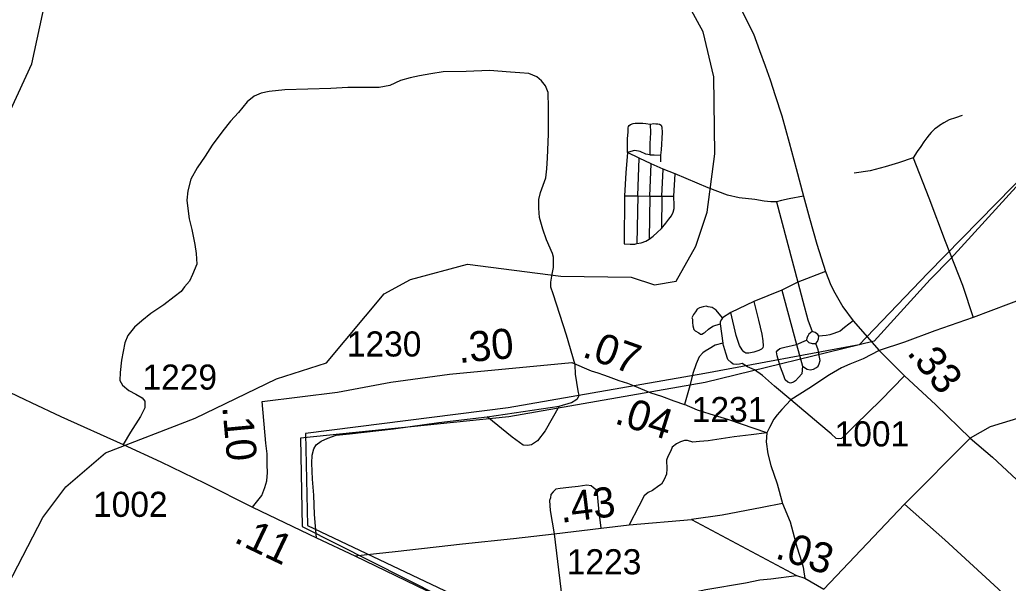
# Model space of a CAD drawing. Extents: x 2290615 to 2522933, y 819489 to 1012715.
# Drawn here: x 2388155 to 2393085, y 888136 to 890944 of the extents above; entities that cross this region are included whole.
import ezdxf

# ---------------------------------------------------------------- set-up
doc = ezdxf.new("R2010")
doc.units = 0
for name, color, linetype in [('Exist Boundary Political City Limit New', 7, 'Continuous'), ('Exist Boundary Political City Limit Old', 7, 'Continuous'), ('Exist Hydrographic Misc Water Feature', 7, 'Continuous'), ('Exist Road Non-System Type 51', 7, 'Continuous'), ('Exist Road Primary NC Attributed', 7, 'Continuous'), ('Exist Road Primary NC Service Mileage Hundredths English Label', 7, 'Continuous'), ('Exist Road Secondary Mileage Hundredths English Label', 7, 'Continuous'), ('Exist Road Secondary Type 51 Attributed', 7, 'Continuous'), ('Exist Road Secondary Type 51 Number Label', 7, 'Continuous'), ('Map Preparation Boundary City Limit Buffer Line', 7, 'Continuous')]:
    doc.layers.add(name, color=color, linetype=linetype)

msp = doc.modelspace()

# ---------------------------------------------------------------- linework, layer by layer
at = {"layer": 'Exist Boundary Political City Limit New'}
msp.add_lwpolyline([(2393362.8, 890373.7), (2392798.4, 889753.9), (2392694.9, 889650.5), (2392416.3, 889342.7), (2391572.9, 889137), (2390593.4, 888966), (2389555.6, 888859.2), (2389564.2, 888418.8), (2390596.7, 887898.2), (2389956.2, 887761.5), (2390068.6, 886905.3)], dxfattribs=at)
at = {"layer": 'Exist Boundary Political City Limit Old'}
msp.add_lwpolyline([(2393362.8, 890373.7), (2392684.2, 889680.7), (2392341, 889324.3), (2391571, 889182.1), (2390591.5, 889011.1), (2389579.5, 888881.7), (2389589.6, 888423.9), (2390631.3, 887930.1), (2390631.8, 887929.9)], dxfattribs=at)
at = {"layer": 'Exist Hydrographic Misc Water Feature'}
for points in [[(2383748.3, 888971.7), (2384365.3, 888954.3), (2385105.3, 889047.1), (2385735.3, 889315.7), (2386132.2, 889529), (2386581.2, 889704), (2386835.3, 889849), (2387338.5, 890082.2), (2387673.2, 890156.7), (2387970.3, 890352.8), (2388110.4, 890496.3), (2388215.4, 890723.8), (2388349.3, 891339.9), (2388438.3, 891550.4), (2388619.3, 891728.4), (2388801.2, 891837.6)], [(2387945.3, 887837.2), (2388270.3, 888464.4), (2388385.4, 888616.8), (2388583.2, 888785.7), (2389030.2, 888958.4), (2389436.2, 889155.5), (2389685.4, 889234.6), (2389972.3, 889578), (2390104.3, 889649), (2390387.3, 889726.3), (2390854.2, 889666.5), (2391204.2, 889661.2), (2391321.3, 889623.4), (2391429.4, 889640.9), (2391527.2, 889815.6), (2391583.3, 889985.4), (2391621.3, 890275.8), (2391616.4, 890659.6), (2391563.3, 890883.9), (2391306.3, 891356), (2391143.3, 891736.7), (2391133.3, 891861)]]:
    msp.add_lwpolyline(points, dxfattribs=at)
at = {"layer": 'Exist Road Non-System Type 51'}
for p, q in [((2391244.7, 890254.1), (2391185.8, 890282.7)), ((2391350.4, 890268.6), (2391351.2, 890235.5)), ((2391237.6, 890067.1), (2391244.7, 890254.1)), ((2391303.7, 890225.4), (2391244.7, 890254.1)), ((2391296.5, 890065.6), (2391303.7, 890225.4)), ((2391364, 890200.1), (2391303.7, 890225.4)), ((2391356.8, 890065.6), (2391364, 890200.1)), ((2391423, 890175.7), (2391364, 890200.1)), ((2391417.2, 890064.2), (2391423, 890175.7)), ((2391171.5, 890067.1), (2391237.6, 890067.1)), ((2391237.6, 890067.1), (2391231.8, 889828.4)), ((2391237.6, 890067.1), (2391296.5, 890065.6)), ((2391296.5, 890065.6), (2391293.6, 889850)), ((2391296.5, 890065.6), (2391356.8, 890065.6)), ((2391356.8, 890065.6), (2391355.4, 889904.6)), ((2391356.8, 890065.6), (2391417.2, 890064.2)), ((2391929.3, 890036.4), (2392034.9, 889636.1)), ((2392173.5, 889689.5), (2392034.9, 889636.1)), ((2392034.9, 889636.1), (2391955.5, 889597)), ((2391955.5, 889597), (2391816.3, 889539.3)), ((2391955.5, 889597), (2392029, 889326.1)), ((2391816.3, 889539.3), (2391701.1, 889485.8)), ((2393173.6, 889559.3), (2392909.1, 889460.3)), ((2391701.1, 889485.8), (2391659.3, 889459.2)), ((2391647.8, 889429.1), (2391661.1, 889333.2)), ((2392029, 889326.1), (2392078.8, 889346.7)), ((2392029, 889326.1), (2392058.4, 889218.6)), ((2390486.1, 888965.7), (2390845.3, 889018.5))]:
    msp.add_line(p, q, dxfattribs=at)
for points in [[(2390845.3, 889018.5), (2390907.2, 889037.2), (2390928.9, 889049.5), (2390936.8, 889057.6), (2390944.6, 889071.7), (2390940.2, 889095.8), (2390926.8, 889178.2), (2390925.4, 889224), (2390882.5, 889373), (2390832.6, 889526.2), (2390816, 889577.9), (2390803.4, 889611.9), (2390803.3, 889635.9), (2390810.6, 889675.8), (2390816.2, 889710), (2390817.7, 889739), (2390817.7, 889761.3), (2390811.4, 889779.9), (2390782.4, 889847.5), (2390763.8, 889901.2), (2390747, 889958.9), (2390744.3, 890004.8), (2390743.7, 890048.8), (2390751.3, 890083), (2390778.3, 890156.1), (2390783.4, 890200.8), (2390786.8, 890255.7), (2390792, 890374.1), (2390792, 890504.6), (2390790.3, 890581.8), (2390776.5, 890614.5), (2390757.7, 890640.2), (2390733.7, 890659.1), (2390694.2, 890676.3), (2390649.5, 890679.5), (2390603.3, 890683.1), (2390498.6, 890691.7), (2390382, 890686.5), (2390267.5, 890684.5), (2390205.3, 890674.5), (2390148.6, 890664.2), (2390101.5, 890654.8), (2390053.4, 890641.1), (2390000.2, 890617), (2389947.1, 890606.7), (2389863, 890606.7), (2389790.6, 890606.1), (2389706.6, 890601), (2389477.9, 890595.6), (2389398.9, 890587), (2389359.5, 890578.4), (2389323.5, 890563), (2389289.1, 890535.5), (2389246.3, 890482.3), (2389207, 890438.3), (2389167.6, 890389.9), (2389114.6, 890319.3), (2389079.1, 890263.7), (2389040, 890206.1), (2389008.9, 890149.8), (2388994.1, 890090.9), (2388988.9, 890044.6), (2388994.7, 889990.2), (2389000.9, 889951.9), (2389012.9, 889898.7), (2389028.4, 889824.9), (2389035.2, 889778.5), (2389038.7, 889725.3), (2389017.2, 889674.1), (2389001.5, 889641.9), (2388977.5, 889613.6), (2388960.3, 889590.7), (2388924.7, 889562.9), (2388873, 889524.1), (2388808.6, 889480.4), (2388764.2, 889443.2), (2388727, 889411.6), (2388694.1, 889371.5), (2388679.8, 889334.3), (2388671.2, 889291.4), (2388662.6, 889247), (2388655.5, 889186.8), (2388654, 889146.7), (2388668.3, 889122.4), (2388699.8, 889096.6), (2388734.2, 889078), (2388765.7, 889060.8), (2388778.5, 889043.6), (2388778.5, 889010.7), (2388757.1, 888966.3), (2388707, 888889), (2388671.2, 888827.4)], [(2392854.3, 890467.2), (2392821.2, 890455.2), (2392790.4, 890444.6), (2392762.6, 890429.6), (2392741.6, 890417.6), (2392731.2, 890408.5), (2392719.2, 890399.9), (2392700.9, 890383), (2392690.3, 890370.6), (2392678.9, 890355.5), (2392663.4, 890336.4), (2392648.4, 890312.3), (2392630.4, 890286.8), (2392610.8, 890256.7)], [(2391185.8, 890282.7), (2391185.8, 890350.3), (2391188.7, 890386.2), (2391188.7, 890397.7), (2391190.1, 890404.9), (2391191.6, 890412.1), (2391194.5, 890416.4), (2391201.6, 890422.2), (2391214.6, 890426.5), (2391224.6, 890429.4), (2391236.1, 890429.4), (2391263.2, 890428.9), (2391277.8, 890426.5), (2391299.3, 890423.6)], [(2391299.3, 890423.6), (2391300.8, 890380.5), (2391297.9, 890327.3), (2391297.9, 890285.6), (2391296.5, 890271.2)], [(2391299.3, 890423.6), (2391317.7, 890426.5), (2391327.4, 890425.7), (2391337.9, 890425.3), (2391345.3, 890423.6), (2391353.6, 890418.4), (2391357.3, 890408.7), (2391358.3, 890381.9), (2391353.6, 890295.3), (2391350.4, 890268.6)], [(2391185.8, 890282.7), (2391177.2, 890180.7), (2391171.5, 890067.1)], [(2391296.5, 890271.2), (2391278.2, 890274.7), (2391249.1, 890288), (2391222.1, 890292), (2391214, 890291.2), (2391185.8, 890282.7)], [(2391296.5, 890271.2), (2391318.7, 890270.8), (2391350.4, 890268.6)], [(2392610.8, 890256.7), (2392537.2, 890231.1), (2392471.1, 890211.6), (2392395.9, 890190.5), (2392316.3, 890180)], [(2392610.8, 890256.7), (2392689.2, 890056.7), (2392770.2, 889839.9), (2392856.9, 889621.2), (2392909.1, 889460.3)], [(2391929.3, 890036.4), (2391901, 890036.7), (2391867.9, 890039.6), (2391820.5, 890048.2), (2391742.9, 890056.8), (2391684, 890069.8), (2391587.8, 890107.1), (2391423, 890175.7)], [(2391171.5, 890067.1), (2391170, 889827), (2391198.8, 889825.6), (2391221.8, 889825.6), (2391231.8, 889828.4)], [(2391355.4, 889904.6), (2391376.9, 889930.5), (2391392.7, 889950.6), (2391405.7, 889966.4), (2391414.3, 889985.1), (2391418.6, 890003.8), (2391418.6, 890034), (2391417.2, 890049.8), (2391417.2, 890064.2)], [(2392063.8, 890065.7), (2391991.5, 890051.5), (2391953.6, 890043), (2391929.3, 890036.4)], [(2391293.6, 889850), (2391313.7, 889865.8), (2391333.8, 889883.1), (2391355.4, 889904.6)], [(2391231.8, 889828.4), (2391254.8, 889832.8), (2391277.8, 889839.9), (2391293.6, 889850)], [(2392034.9, 889636.1), (2392060.1, 889542.5), (2392085.4, 889448.9), (2392106.2, 889391.1)], [(2391816.3, 889539.3), (2391839.5, 889447.6), (2391856.4, 889377.9), (2391860.8, 889343.8), (2391863.2, 889319.9), (2391861.4, 889309.8), (2391853.5, 889301.9), (2391841.5, 889295.6), (2391815.7, 889287.3), (2391791.6, 889283), (2391775.6, 889282.7), (2391765.6, 889288.7), (2391757.4, 889298.6), (2391745.3, 889320.5), (2391728.4, 889370.2), (2391701.1, 889485.8)], [(2391659.3, 889459.2), (2391628.8, 889496.8), (2391608.6, 889510.6), (2391588.7, 889514.2), (2391578.6, 889516.2), (2391562.7, 889513.9), (2391544.7, 889507.8), (2391532.7, 889501.5), (2391525, 889489.3), (2391515.2, 889475.3), (2391507.5, 889459.2), (2391509.6, 889451.3), (2391509.6, 889435.3), (2391511.9, 889419.2), (2391516.2, 889401.3), (2391524.2, 889393.5), (2391542.4, 889383.6), (2391550.4, 889377.7), (2391556.4, 889377.8), (2391564.5, 889381.9), (2391572.3, 889386), (2391590, 889402.4), (2391611.9, 889416.7), (2391647.8, 889429.1)], [(2391659.3, 889459.2), (2391655.5, 889451.1), (2391647.6, 889439.1), (2391647.8, 889429.1)], [(2392909.1, 889460.3), (2392718, 889393.4), (2392566.8, 889337.3), (2392441.1, 889295.6), (2392361.9, 889254.5), (2392294.3, 889227.7), (2392252.5, 889209.2), (2392193.1, 889174.3), (2392090, 889107.1), (2392000.7, 889049.8)], [(2392310.9, 889444.6), (2392267.8, 889411.3), (2392246.2, 889393), (2392214.3, 889380.5), (2392194.3, 889374.3), (2392176.5, 889370.2), (2392140.5, 889367.7)], [(2392106.2, 889391.1), (2392090.3, 889377), (2392086.4, 889370.9), (2392080.7, 889358.8), (2392078.8, 889346.7)], [(2392140.5, 889367.7), (2392134.4, 889375.4), (2392122.2, 889385.3), (2392106.2, 889391.1)], [(2391661.1, 889333.2), (2391623.1, 889322.7), (2391593.4, 889304.4), (2391573.5, 889292), (2391561.7, 889283.9), (2391543.9, 889263.8), (2391528.5, 889229.5), (2391511, 889181.2), (2391496, 889119.2), (2391470.7, 889026.4)], [(2392000.7, 889049.8), (2391919.8, 889118.7), (2391859.2, 889171.9), (2391818.9, 889199.4), (2391784.6, 889214.8), (2391758.4, 889230.6), (2391744.4, 889228.4), (2391730.5, 889226.2), (2391712.4, 889227.9), (2391702.3, 889235.9), (2391686.1, 889251.6), (2391675.7, 889283.4), (2391661.1, 889333.2)], [(2392058.4, 889218.6), (2392055, 889180.5), (2392039.3, 889162.2), (2392023.4, 889144.2), (2392013.5, 889138), (2391999.6, 889133.8), (2391985.5, 889137.6), (2391971.4, 889149.4), (2391965.2, 889169.4), (2391948.6, 889213.1), (2391931.9, 889268.9), (2391929.5, 889288.8), (2391935.5, 889296.9), (2391945.4, 889305.1), (2391957.2, 889309.2), (2391971.3, 889313.3), (2392029, 889326.1)], [(2392058.4, 889218.6), (2392082.7, 889202.8), (2392096.6, 889199), (2392112.7, 889203.3), (2392128.5, 889211.5), (2392136.5, 889217.6), (2392142.4, 889229.7), (2392146.1, 889245.7), (2392141.7, 889271.7), (2392137.3, 889299.5), (2392125, 889331.4)], [(2392078.8, 889346.7), (2392090.9, 889335), (2392107, 889331.1), (2392125, 889331.4)], [(2392125, 889331.4), (2392132.8, 889341.6), (2392138.7, 889353.6), (2392140.5, 889367.7)], [(2392567.1, 889169.3), (2392448.6, 889047.7), (2392322.3, 888926.1), (2392271, 888873.4), (2392253.3, 888857.2), (2392239.2, 888855.1), (2392227.3, 888857), (2392200.9, 888880.5), (2392140.2, 888931.6), (2392000.7, 889049.8)], [(2391880.9, 888886.2), (2391691.1, 888950.5), (2391598.1, 888979.2), (2391535.1, 888999.2), (2391470.7, 889026.4)], [(2392000.7, 889049.8), (2391955.4, 889001.3), (2391931.7, 888974.9), (2391915.8, 888953.4), (2391894.6, 888912.4), (2391880.9, 888886.2)], [(2393378.4, 889044.2), (2393151.6, 888963.1), (2392994.3, 888915), (2392895.1, 888859.7)], [(2390845.3, 889018.5), (2390774.9, 888895.5), (2390737.8, 888845.2), (2390707.9, 888826.7), (2390688.1, 888822.5), (2390666, 888824.2), (2390611.6, 888863.4), (2390486.1, 888965.7)], [(2389634.4, 888362.5), (2389624.8, 888478.4), (2389621.5, 888574.3), (2389614.4, 888654.2), (2389611.3, 888734.2), (2389612.9, 888774), (2389622.4, 888806.2), (2389634.2, 888826.3), (2389658, 888844.7), (2389691.7, 888859.1), (2389733.5, 888873.6), (2389799.4, 888880.5), (2390019.1, 888905.5), (2390244.6, 888936.6), (2390486.1, 888965.7)], [(2391880.9, 888886.2), (2391803.1, 888875.2), (2391717.2, 888866.1), (2391587.6, 888846.4), (2391545.5, 888841.8), (2391511.6, 888839.4), (2391485.5, 888847), (2391469.5, 888846.7), (2391449.5, 888840.5), (2391429.8, 888830.3), (2391408, 888814), (2391402.1, 888795.9), (2391386.5, 888767.7), (2391380.8, 888749.6), (2391381.4, 888705.6), (2391379.7, 888679.6), (2391368.2, 888653.5), (2391356.3, 888629.4), (2391342.5, 888621.2), (2391310.8, 888598.7), (2391289, 888588.4), (2391269.2, 888572.2), (2391242, 888519.8), (2391195.1, 888427.3)], [(2391880.9, 888886.2), (2391877.6, 888840.2), (2391886.2, 888780.4), (2391901, 888722.5), (2391932.2, 888631), (2391959.6, 888533.4)], [(2392895.1, 888859.7), (2393006.2, 888765.2), (2393150.1, 888629.2), (2393312, 888481.4)], [(2391055.3, 888411.3), (2391044.2, 888491.3), (2391039.7, 888543.2), (2391037.1, 888581.1), (2391028.9, 888600.9), (2391016.7, 888610.9), (2391004.7, 888620.8), (2390982.5, 888624.5), (2390940.6, 888617.7), (2390892.8, 888613.2), (2390850.7, 888608.7), (2390828.9, 888604.4), (2390815, 888592.2), (2390803.1, 888578.1), (2390801.4, 888562), (2390797.6, 888547.8), (2390800.2, 888497.9), (2390819.8, 888382.3), (2390870.6, 887968.4), (2390919.7, 887637.8), (2390948.5, 887418.2), (2390967.2, 887224.5)], [(2391959.6, 888533.4), (2391857.9, 888514.1), (2391658.4, 888475.5), (2391504.8, 888453.4)], [(2391959.6, 888533.4), (2391996.7, 888441.9), (2392030.4, 888318.4), (2392055.5, 888238.8), (2392062.1, 888216.7), (2392066, 888192.8), (2392070.5, 888161)], [(2392567, 888530.9), (2392767.8, 888352.2), (2393035, 888107.9), (2393221.2, 887934.4), (2393347.1, 887809.2)]]:
    msp.add_lwpolyline(points, dxfattribs=at)
at = {"layer": 'Exist Road Primary NC Attributed'}
for points in [[(2390614.1, 887907.6), (2390870.6, 887968.4), (2391208.8, 888033.1), (2391341.4, 888055.2), (2391577.3, 888104.3), (2391774.8, 888139.1), (2391846.6, 888154), (2391900.5, 888158.6), (2392028.3, 888174.5)], [(2392028.3, 888174.5), (2392070.5, 888161), (2392165.2, 888106.2)]]:
    msp.add_lwpolyline(points, dxfattribs=at)
at = {"layer": 'Exist Road Secondary Type 51 Attributed'}
for points in [[(2391743.7, 891011.5), (2391814.4, 890873.2), (2391844.4, 890790.5), (2391873, 890713.8), (2391897, 890644.6), (2391922.6, 890566.4), (2391955.6, 890465.7), (2391991.7, 890331.9), (2392027.7, 890202.6), (2392063.8, 890065.7), (2392093.9, 889956), (2392130.5, 889825.5), (2392173.5, 889689.5), (2392199.2, 889622.2), (2392219.3, 889583.5), (2392239.3, 889549.1), (2392259.3, 889513.3), (2392310.9, 889444.6), (2392441.1, 889295.6), (2392567.1, 889169.3), (2392722.9, 889025.4), (2392895.1, 888859.7), (2392567, 888530.9), (2392165.2, 888106.2)], [(2386835.3, 889849), (2386963.3, 889759.7), (2387075.5, 889674.2), (2387182.6, 889595.7), (2387294.3, 889507.6), (2387377.4, 889438.9), (2387479, 889373), (2387612.1, 889302.8), (2387673.6, 889267), (2387739.2, 889235.1), (2387837.6, 889198.3), (2387910, 889169.5), (2387984.4, 889142.3), (2388072.8, 889103.5), (2388211.8, 889037.4), (2388360.5, 888967.4), (2388671.2, 888827.4), (2388858.7, 888741.5), (2389077.7, 888634.1), (2389315.3, 888515.2)], [(2389363.4, 889041.9), (2389740.3, 889088), (2390005.1, 889138.1), (2390298.5, 889178.2), (2390908.2, 889236)], [(2390908.2, 889236), (2391005.6, 889195.4), (2391038.5, 889184), (2391067.1, 889173.9), (2391089.5, 889165.7), (2391143, 889146.7), (2391185.9, 889132.4), (2391218.8, 889119.5), (2391301.8, 889085.1), (2391356.2, 889068), (2391417.8, 889045), (2391470.7, 889026.4)], [(2389315.3, 888515.2), (2389362.5, 888573.9), (2389378.2, 888614), (2389386.8, 888646.9), (2389391.1, 888688.5), (2389389.7, 888725.7), (2389388.3, 888781.5), (2389382.5, 888834.5), (2389363.4, 889041.9)], [(2389315.3, 888515.2), (2389634.4, 888362.5), (2389825.5, 888273.1)], [(2389825.5, 888273.1), (2390027.2, 888293.8), (2390362.6, 888332.1), (2390618.2, 888359.6), (2390819.8, 888382.3), (2391055.3, 888411.3), (2391195.1, 888427.3), (2391504.8, 888453.4), (2392028.3, 888174.5)], [(2389825.5, 888273.1), (2390386.9, 888002.5), (2390614.1, 887907.6)]]:
    msp.add_lwpolyline(points, dxfattribs=at)
at = {"layer": 'Map Preparation Boundary City Limit Buffer Line'}
msp.add_lwpolyline([(2393362.8, 890373.7), (2392798.4, 889753.9), (2392694.9, 889650.5), (2392416.3, 889342.7), (2391572.9, 889137), (2390593.4, 888966), (2389555.6, 888859.2), (2389564.2, 888418.8), (2390596.7, 887898.2), (2389956.2, 887761.5), (2390068.6, 886905.3)], dxfattribs=at)

# ---------------------------------------------------------------- texts
at = {"layer": 'Exist Road Primary NC Service Mileage Hundredths English Label'}
msp.add_text('.03', height=150, rotation=342.2587, dxfattribs=at).set_placement((2391917.3, 888262.5))
at = {"layer": 'Exist Road Secondary Mileage Hundredths English Label'}
for s, rotation, p in [('.30', 5.4148, (2390346.4, 889233)), ('.07', 340.4272, (2390954.9, 889266.7)), ('.33', 309.2292, (2392575.2, 889283.2)), ('.04', 342.4655, (2391115.7, 888934.2)), ('.10', 275.2711, (2389164.9, 889016.4)), ('.43', 7.0201, (2390855.3, 888437.1)), ('.11', 334.4363, (2389217.9, 888343.8))]:
    msp.add_text(s, height=150, rotation=rotation, dxfattribs=at).set_placement(p)
at = {"layer": 'Exist Road Secondary Type 51 Number Label'}
for s, p in [('1230', (2389786.4, 889266)), ('1229', (2388767.4, 889101)), ('1231', (2391506.6, 888939.2)), ('1001', (2392218.7, 888817.9)), ('1223', (2390883.3, 888180.9))]:
    msp.add_text(s, height=125, dxfattribs=at).set_placement(p)
msp.add_text('1002', height=125, rotation=360, dxfattribs=at).set_placement((2388520.7, 888467))

doc.saveas('drawing.dxf')
